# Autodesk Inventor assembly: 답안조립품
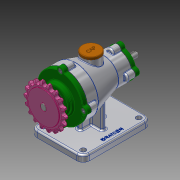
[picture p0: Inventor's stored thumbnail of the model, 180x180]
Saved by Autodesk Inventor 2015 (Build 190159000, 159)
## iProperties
Created: 2020-12
Part Number: 답안조립품
Document SubType Name: Assembly
Designer: Lineart
Author: Lineart
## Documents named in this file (15)
- C:\Users\Lineart\Desktop\701206V1019\답안조립품.iam
- C:\Users\Lineart\Desktop\701206V1019\본체.ipt
- C:\Users\Lineart\Desktop\701206V1019\개스킷 A.ipt
- C:\Users\Lineart\Desktop\701206V1019\개스킷 B.ipt
- C:\Users\Lineart\Desktop\701206V1019\앞커버.ipt
- C:\Users\Lineart\Desktop\701206V1019\베어링 6203.ipt
- C:\Users\Lineart\Desktop\701206V1019\축.ipt
- C:\Users\Lineart\Desktop\701206V1019\뒤커버.ipt
- C:\Users\Lineart\Desktop\701206V1019\베어링 6200.ipt
- C:\Users\Lineart\Desktop\701206V1019\오일 실 17 30 8.ipt
- C:\Users\Lineart\Desktop\701206V1019\오일 실 10 20 7.ipt
- C:\Users\Lineart\Desktop\701206V1019\볼트 M5.ipt
- C:\Users\Lineart\Desktop\701206V1019\키 4x4x14.ipt
- C:\Users\Lineart\Desktop\701206V1019\스프로킷.ipt
- C:\Users\Lineart\Desktop\701206V1019\마개.ipt
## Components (2 placed, 2 different names)
1. 개스킷 A:1
2. 개스킷 B:1
